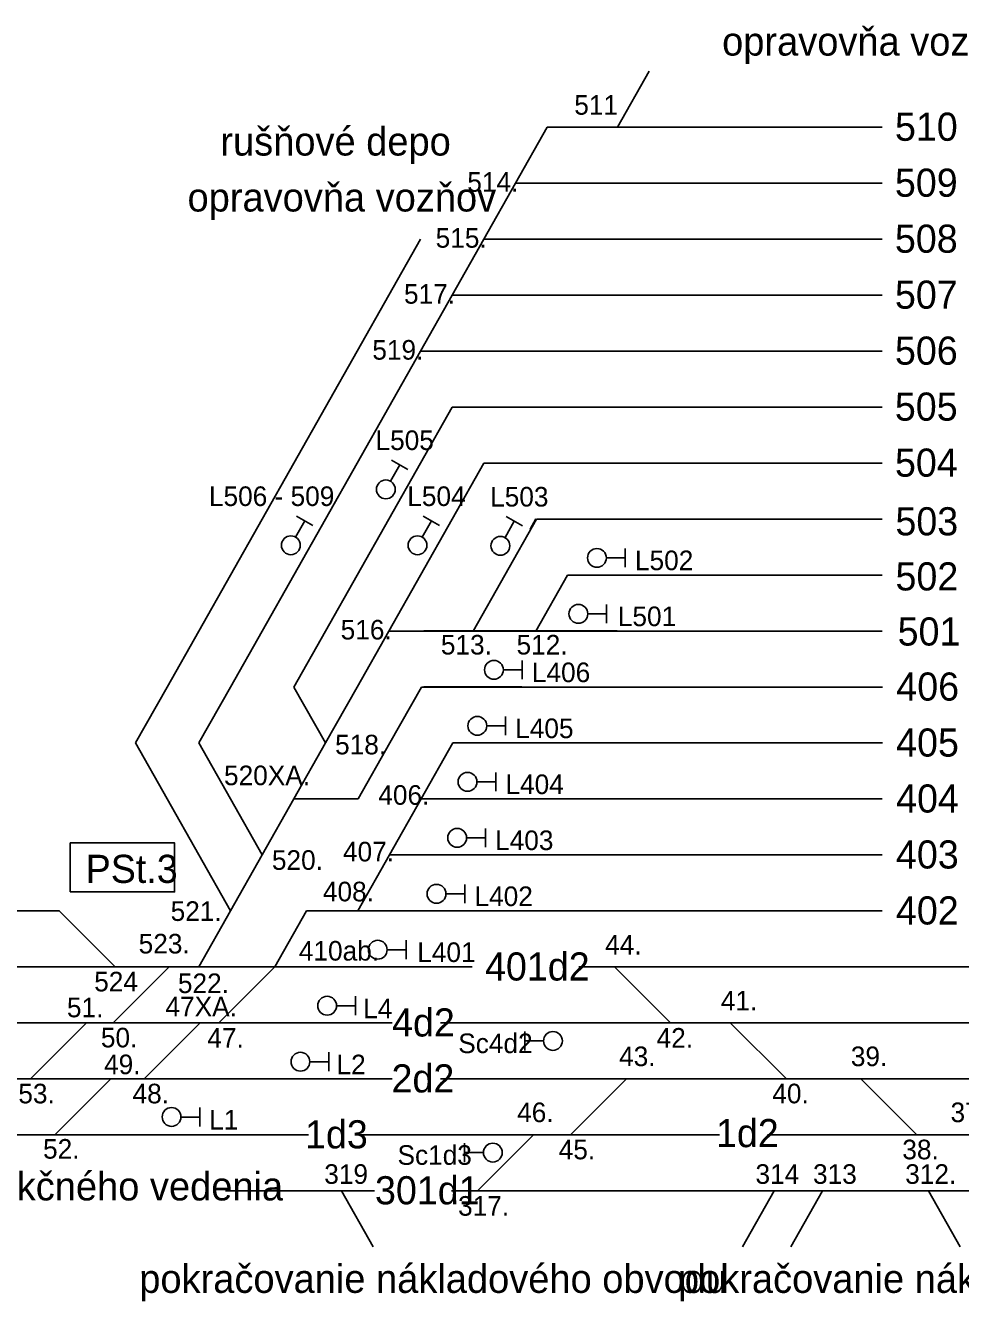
# Model space of a CAD drawing. Extents: x -119 to 851, y -238 to 59.
# Drawn here: x 437.12 to 470.49, y -115.25 to -69.7 of the extents above; entities that cross this region are included whole.
import ezdxf

# ---------------------------------------------------------------- set-up
doc = ezdxf.new("R2010")
doc.units = 0
for name, color, linetype in [('budova', 7, 'Continuous'), ('Level 2', 7, 'Continuous'), ('netlač', 7, 'Continuous'), ('PU_navestidla', 7, 'Continuous'), ('PU_oznacenie navestidiel', 7, 'Continuous'), ('PU_stan_kolaje', 7, 'Continuous'), ('PU_vlecky', 7, 'Continuous')]:
    doc.layers.add(name, color=color, linetype=linetype)

msp = doc.modelspace()

# ---------------------------------------------------------------- linework, layer by layer
at = {"layer": 'budova'}
msp.add_lwpolyline([(438.715, -100.631), (442.443, -100.631), (442.443, -98.882), (438.715, -98.882)], close=True, dxfattribs=at)
msp.add_lwpolyline([(438.715, -100.631), (442.443, -100.631), (442.443, -98.882), (438.715, -98.882)], close=True, dxfattribs=at)
at = {"layer": 'Level 2'}
for p, q in [((458.236, -91.313), (451.337, -91.313)), ((458.236, -91.313), (451.337, -91.313)), ((454.836, -93.312), (451.337, -93.312)), ((454.836, -93.312), (451.337, -93.312)), ((453.736, -99.309), (450.114, -99.309)), ((453.736, -99.309), (450.114, -99.309)), ((438.339, -101.308), (436.556, -101.308)), ((438.339, -101.308), (436.556, -101.308)), ((447.937, -101.308), (447.837, -101.308)), ((447.937, -101.308), (447.837, -101.308)), ((452.836, -101.308), (447.937, -101.308)), ((452.836, -101.308), (447.937, -101.308)), ((436.556, -103.307), (442.248, -103.307)), ((436.556, -103.307), (442.248, -103.307)), ((421.041, -107.305), (450.209, -107.305)), ((421.041, -107.305), (450.209, -107.305)), ((451.932, -107.305), (474.492, -107.305)), ((451.932, -107.305), (474.492, -107.305)), ((444.263, -111.303), (449.573, -111.303)), ((444.263, -111.303), (449.573, -111.303))]:
    msp.add_line(p, q, dxfattribs=at)
msp.add_lwpolyline([(455.132, -87.681), (455.336, -87.315)], dxfattribs=at)
msp.add_lwpolyline([(455.132, -87.681), (455.336, -87.315)], dxfattribs=at)
at = {"layer": 'netlač'}
for p, q in [((455.734, -73.33), (467.694, -73.33)), ((454.604, -75.328), (467.694, -75.328)), ((454.604, -75.328), (467.694, -75.328)), ((453.474, -77.327), (467.694, -77.327)), ((453.474, -77.327), (467.694, -77.327)), ((452.344, -79.325), (467.694, -79.325)), ((452.344, -79.325), (467.694, -79.325)), ((451.214, -81.324), (467.694, -81.324)), ((451.214, -81.324), (467.694, -81.324)), ((467.694, -83.32), (452.344, -83.322)), ((467.694, -83.32), (452.344, -83.322)), ((453.474, -85.321), (467.694, -85.321)), ((453.474, -85.321), (467.694, -85.321)), ((455.36, -87.319), (467.694, -87.319)), ((455.36, -87.319), (467.694, -87.319)), ((456.461, -89.318), (467.694, -89.318)), ((456.461, -89.318), (467.694, -89.318)), ((450.085, -91.316), (467.694, -91.316)), ((450.085, -91.316), (467.694, -91.316)), ((451.249, -93.315), (467.711, -93.315)), ((451.249, -93.315), (467.711, -93.315)), ((452.373, -95.313), (467.706, -95.313)), ((452.373, -95.313), (467.706, -95.313)), ((446.695, -97.311), (448.989, -97.311)), ((446.695, -97.311), (448.989, -97.311)), ((451.243, -97.312), (467.702, -97.312)), ((451.243, -97.312), (467.702, -97.312)), ((450.113, -99.31), (467.698, -99.31)), ((450.113, -99.31), (467.698, -99.31)), ((447.155, -101.308), (467.694, -101.308)), ((447.155, -101.308), (467.694, -101.308)), ((442.248, -103.307), (453.064, -103.307)), ((442.248, -103.307), (453.064, -103.307)), ((456.871, -103.307), (473.479, -103.307)), ((456.871, -103.307), (473.479, -103.307)), ((450.209, -105.306), (427.162, -105.306)), ((450.209, -105.306), (427.162, -105.306)), ((474.492, -105.306), (451.932, -105.306)), ((474.492, -105.306), (451.932, -105.306)), ((447.22, -109.302), (421.041, -109.302)), ((447.22, -109.302), (421.041, -109.302)), ((448.964, -109.302), (461.887, -109.302)), ((448.964, -109.302), (461.887, -109.302)), ((463.603, -109.302), (474.492, -109.302)), ((463.603, -109.302), (474.492, -109.302)), ((484.296, -111.301), (452.322, -111.301)), ((484.296, -111.301), (452.322, -111.301))]:
    msp.add_line(p, q, dxfattribs=at)
at = {"layer": 'PU_navestidla'}
for p, q in [((450.479, -85.38), (450.148, -85.965)), ((450.479, -85.38), (450.148, -85.965)), ((450.185, -85.214), (450.77, -85.545)), ((450.185, -85.214), (450.77, -85.545)), ((447.089, -87.378), (446.758, -87.963)), ((447.089, -87.378), (446.758, -87.963)), ((446.795, -87.212), (447.38, -87.543)), ((446.795, -87.212), (447.38, -87.543)), ((451.609, -87.378), (451.278, -87.963)), ((451.609, -87.378), (451.278, -87.963)), ((451.315, -87.212), (451.9, -87.543)), ((451.315, -87.212), (451.9, -87.543)), ((454.567, -87.397), (454.237, -87.982)), ((454.567, -87.397), (454.237, -87.982)), ((454.274, -87.231), (454.859, -87.562)), ((454.274, -87.231), (454.859, -87.562)), ((458.525, -88.369), (458.525, -89.041)), ((458.525, -88.369), (458.525, -89.041)), ((458.525, -88.706), (457.853, -88.706)), ((458.525, -88.706), (457.853, -88.706)), ((457.862, -90.367), (457.862, -91.039)), ((457.862, -90.367), (457.862, -91.039)), ((457.862, -90.705), (457.19, -90.705)), ((457.862, -90.705), (457.19, -90.705)), ((454.849, -92.366), (454.849, -93.038)), ((454.849, -92.366), (454.849, -93.038)), ((454.849, -92.704), (454.177, -92.704)), ((454.849, -92.704), (454.177, -92.704)), ((454.255, -94.702), (453.583, -94.702)), ((454.255, -94.702), (453.583, -94.702)), ((454.255, -94.365), (454.255, -95.037)), ((454.255, -94.365), (454.255, -95.037)), ((453.905, -96.363), (453.905, -97.035)), ((453.905, -96.363), (453.905, -97.035)), ((453.905, -96.701), (453.233, -96.701)), ((453.905, -96.701), (453.233, -96.701)), ((453.535, -98.363), (453.535, -99.035)), ((453.535, -98.363), (453.535, -99.035)), ((453.535, -98.7), (452.863, -98.7)), ((453.535, -98.7), (452.863, -98.7)), ((452.799, -100.361), (452.799, -101.033)), ((452.799, -100.361), (452.799, -101.033)), ((452.799, -100.699), (452.127, -100.699)), ((452.799, -100.699), (452.127, -100.699)), ((450.701, -102.359), (450.701, -103.031)), ((450.701, -102.359), (450.701, -103.031)), ((450.701, -102.696), (450.029, -102.696)), ((450.701, -102.696), (450.029, -102.696)), ((448.894, -104.694), (448.222, -104.694)), ((448.894, -104.694), (448.222, -104.694)), ((448.894, -104.357), (448.894, -105.029)), ((448.894, -104.357), (448.894, -105.029)), ((454.938, -106.287), (454.938, -105.615)), ((454.938, -106.287), (454.938, -105.615)), ((454.938, -105.949), (455.61, -105.949)), ((454.938, -105.949), (455.61, -105.949)), ((447.941, -106.356), (447.941, -107.028)), ((447.941, -106.356), (447.941, -107.028)), ((447.941, -106.693), (447.269, -106.693)), ((447.941, -106.693), (447.269, -106.693)), ((443.342, -108.331), (443.342, -109.002)), ((443.342, -108.331), (443.342, -109.002)), ((443.342, -108.668), (442.67, -108.668)), ((443.342, -108.668), (442.67, -108.668)), ((452.792, -110.275), (452.792, -109.603)), ((452.792, -110.275), (452.792, -109.603)), ((452.792, -109.937), (453.464, -109.937)), ((452.792, -109.937), (453.464, -109.937))]:
    msp.add_line(p, q, dxfattribs=at)
for centre in [(449.981, -86.257), (449.981, -86.257), (446.592, -88.255), (446.592, -88.255), (451.111, -88.255), (451.111, -88.255), (454.07, -88.274), (454.07, -88.274), (457.517, -88.705), (457.517, -88.705), (456.854, -90.703), (456.854, -90.703), (453.841, -92.702), (453.841, -92.702), (453.247, -94.701), (453.247, -94.701), (452.897, -96.699), (452.897, -96.699), (452.527, -98.699), (452.527, -98.699), (451.791, -100.697), (451.791, -100.697), (449.693, -102.695), (449.693, -102.695), (447.886, -104.693), (447.886, -104.693), (455.946, -105.951), (455.946, -105.951), (446.933, -106.692), (446.933, -106.692), (442.334, -108.666), (442.334, -108.666), (453.8, -109.939), (453.8, -109.939)]:
    msp.add_circle(centre, 0.336, dxfattribs=at)
at = {"layer": 'PU_stan_kolaje'}
for points in [[(458.246, -73.33), (459.375, -71.331)], [(454.604, -75.328), (455.734, -73.33)], [(454.604, -75.328), (455.734, -73.33)], [(453.474, -77.327), (454.604, -75.328)], [(453.474, -77.327), (454.604, -75.328)], [(450.085, -79.325), (451.214, -77.327)], [(450.085, -79.325), (451.214, -77.327)], [(452.344, -79.325), (453.474, -77.327)], [(452.344, -79.325), (453.474, -77.327)], [(448.955, -81.324), (450.085, -79.325)], [(448.955, -81.324), (450.085, -79.325)], [(451.214, -81.324), (452.344, -79.325)], [(451.214, -81.324), (452.344, -79.325)], [(447.825, -83.322), (448.955, -81.324)], [(447.825, -83.322), (448.955, -81.324)], [(450.085, -83.322), (451.214, -81.324)], [(450.085, -83.322), (451.214, -81.324)], [(446.695, -85.321), (447.825, -83.322)], [(446.695, -85.321), (447.825, -83.322)], [(448.955, -85.321), (450.085, -83.322)], [(448.955, -85.321), (450.085, -83.322)], [(451.214, -85.321), (452.344, -83.322)], [(451.214, -85.321), (452.344, -83.322)], [(445.565, -87.319), (446.695, -85.321)], [(445.565, -87.319), (446.695, -85.321)], [(447.825, -87.319), (448.955, -85.321)], [(447.825, -87.319), (448.955, -85.321)], [(450.085, -87.319), (451.214, -85.321)], [(450.085, -87.319), (451.214, -85.321)], [(452.344, -87.319), (453.474, -85.321)], [(452.344, -87.319), (453.474, -85.321)], [(444.435, -89.318), (445.565, -87.319)], [(444.435, -89.318), (445.565, -87.319)], [(446.695, -89.318), (447.825, -87.319)], [(446.695, -89.318), (447.825, -87.319)], [(448.955, -89.318), (450.085, -87.319)], [(448.955, -89.318), (450.085, -87.319)], [(451.214, -89.318), (452.344, -87.319)], [(451.214, -89.318), (452.344, -87.319)], [(454.23, -89.318), (455.36, -87.319)], [(454.23, -89.318), (455.36, -87.319)], [(443.305, -91.316), (444.435, -89.318)], [(443.305, -91.316), (444.435, -89.318)], [(445.565, -91.316), (446.695, -89.318)], [(445.565, -91.316), (446.695, -89.318)], [(447.825, -91.316), (448.955, -89.318)], [(447.825, -91.316), (448.955, -89.318)], [(450.085, -91.316), (451.214, -89.318)], [(450.085, -91.316), (451.214, -89.318)], [(453.1, -91.316), (454.23, -89.318)], [(453.1, -91.316), (454.23, -89.318)], [(455.331, -91.316), (456.461, -89.318)], [(455.331, -91.316), (456.461, -89.318)], [(442.175, -93.315), (443.305, -91.316)], [(442.175, -93.315), (443.305, -91.316)], [(444.435, -93.315), (445.565, -91.316)], [(444.435, -93.315), (445.565, -91.316)], [(446.695, -93.315), (447.825, -91.316)], [(446.695, -93.315), (447.825, -91.316)], [(448.955, -93.315), (450.085, -91.316)], [(448.955, -93.315), (450.085, -91.316)], [(441.045, -95.313), (442.175, -93.315)], [(441.045, -95.313), (442.175, -93.315)], [(443.305, -95.313), (444.435, -93.315)], [(443.305, -95.313), (444.435, -93.315)], [(446.695, -93.315), (447.825, -95.313)], [(446.695, -93.315), (447.825, -95.313)], [(447.825, -95.313), (448.955, -93.315)], [(447.825, -95.313), (448.955, -93.315)], [(450.119, -95.313), (451.249, -93.315)], [(450.119, -95.313), (451.249, -93.315)], [(441.045, -95.313), (442.175, -97.311)], [(441.045, -95.313), (442.175, -97.311)], [(443.305, -95.313), (444.435, -97.311)], [(443.305, -95.313), (444.435, -97.311)], [(446.695, -97.311), (447.825, -95.313)], [(446.695, -97.311), (447.825, -95.313)], [(448.989, -97.311), (450.119, -95.313)], [(448.989, -97.311), (450.119, -95.313)], [(451.243, -97.312), (452.374, -95.312)], [(451.243, -97.312), (452.374, -95.312)], [(442.175, -97.311), (443.305, -99.31)], [(442.175, -97.311), (443.305, -99.31)], [(444.435, -97.311), (445.565, -99.31)], [(444.435, -97.311), (445.565, -99.31)], [(445.565, -99.31), (446.695, -97.311)], [(445.565, -99.31), (446.695, -97.311)], [(450.114, -99.309), (451.244, -97.31)], [(450.114, -99.309), (451.244, -97.31)], [(443.305, -99.31), (444.435, -101.308)], [(443.305, -99.31), (444.435, -101.308)], [(444.435, -101.308), (445.565, -99.31)], [(444.435, -101.308), (445.565, -99.31)], [(448.983, -101.309), (450.113, -99.31)], [(448.983, -101.309), (450.113, -99.31)], [(438.325, -101.308), (440.324, -103.307)], [(438.325, -101.308), (440.324, -103.307)], [(443.305, -103.307), (444.435, -101.308)], [(443.305, -103.307), (444.435, -101.308)], [(446.025, -103.307), (447.155, -101.308)], [(446.025, -103.307), (447.155, -101.308)], [(442.248, -103.307), (440.249, -105.306)], [(442.248, -103.307), (440.249, -105.306)], [(446.025, -103.307), (444.026, -105.306)], [(446.025, -103.307), (444.026, -105.306)], [(458.146, -103.305), (460.145, -105.304)], [(458.146, -103.305), (460.145, -105.304)], [(439.301, -105.306), (437.302, -107.305)], [(439.301, -105.306), (437.302, -107.305)], [(443.356, -105.306), (441.357, -107.305)], [(443.356, -105.306), (441.357, -107.305)], [(462.276, -105.304), (464.276, -107.305)], [(462.276, -105.304), (464.276, -107.305)], [(440.16, -107.305), (438.185, -109.28)], [(440.16, -107.305), (438.185, -109.28)], [(458.566, -107.305), (456.568, -109.302)], [(458.566, -107.305), (456.568, -109.302)], [(466.94, -107.305), (468.937, -109.302)], [(466.94, -107.305), (468.937, -109.302)], [(455.256, -109.302), (453.257, -111.301)], [(455.256, -109.302), (453.257, -111.301)], [(448.396, -111.301), (449.526, -113.299)], [(448.396, -111.301), (449.526, -113.299)], [(462.71, -113.3), (463.84, -111.301)], [(462.71, -113.3), (463.84, -111.301)], [(464.441, -113.3), (465.571, -111.301)], [(464.441, -113.3), (465.571, -111.301)], [(469.356, -111.301), (470.485, -113.299)], [(469.356, -111.301), (470.485, -113.299)]]:
    msp.add_lwpolyline(points, dxfattribs=at)

# ---------------------------------------------------------------- texts
at = {"layer": 'budova'}
msp.add_text('PSt.3', height=1.0044, dxfattribs=at).set_placement((439.268, -100.309))
msp.add_text('PSt.3', height=1.0044, dxfattribs=at).set_placement((439.268, -100.309))
at = {"layer": 'PU_oznacenie navestidiel'}
for s, p in [('511', (456.707, -72.881)), ('514.', (452.889, -75.631)), ('514.', (452.889, -75.631)), ('515.', (451.759, -77.629)), ('515.', (451.759, -77.629)), ('517.', (450.629, -79.628)), ('517.', (450.629, -79.628)), ('519.', (449.499, -81.626)), ('519.', (449.499, -81.626)), ('L505', (449.613, -84.853)), ('L505', (449.613, -84.853)), ('L506 - 509', (443.667, -86.852)), ('L506 - 509', (443.667, -86.852)), ('L504', (450.746, -86.852)), ('L504', (450.746, -86.852)), ('L503', (453.704, -86.871)), ('L503', (453.704, -86.871)), ('L502', (458.873, -89.143)), ('L502', (458.873, -89.143)), ('L501', (458.262, -91.141)), ('L501', (458.262, -91.141)), ('516.', (448.369, -91.618)), ('516.', (448.369, -91.618)), ('513.', (451.946, -92.154)), ('513.', (451.946, -92.154)), ('512.', (454.647, -92.154)), ('512.', (454.647, -92.154)), ('L406', (455.194, -93.141)), ('L406', (455.194, -93.141)), ('L405', (454.598, -95.139)), ('L405', (454.598, -95.139)), ('518.', (448.17, -95.72)), ('518.', (448.17, -95.72)), ('520XA.', (444.206, -96.82)), ('520XA.', (444.206, -96.82)), ('L404', (454.251, -97.137)), ('L404', (454.251, -97.137)), ('406.', (449.713, -97.519)), ('406.', (449.713, -97.519)), ('407.', (448.452, -99.542)), ('407.', (448.452, -99.542)), ('L403', (453.881, -99.137)), ('L403', (453.881, -99.137)), ('520.', (445.915, -99.842)), ('520.', (445.915, -99.842)), ('408.', (447.735, -100.967)), ('408.', (447.735, -100.967)), ('L402', (453.146, -101.135)), ('L402', (453.146, -101.135)), ('521.', (442.301, -101.666)), ('521.', (442.301, -101.666)), ('523.', (441.159, -102.828)), ('523.', (441.159, -102.828)), ('410ab.', (446.877, -103.082)), ('410ab.', (446.877, -103.082)), ('L401', (451.102, -103.133)), ('L401', (451.102, -103.133)), ('44.', (457.808, -102.865)), ('44.', (457.808, -102.865)), ('524', (439.572, -104.182)), ('524', (439.572, -104.182)), ('522.', (442.56, -104.242)), ('522.', (442.56, -104.242)), ('41.', (461.938, -104.864)), ('41.', (461.938, -104.864)), ('51.', (438.599, -105.106)), ('51.', (438.599, -105.106)), ('47XA.', (442.116, -105.072)), ('47XA.', (442.116, -105.072)), ('L4', (449.172, -105.143)), ('L4', (449.172, -105.143)), ('50.', (439.81, -106.181)), ('50.', (439.81, -106.181)), ('47.', (443.61, -106.192)), ('47.', (443.61, -106.192)), ('Sc4d2', (452.566, -106.386)), ('Sc4d2', (452.566, -106.386)), ('42.', (459.646, -106.191)), ('42.', (459.646, -106.191)), ('43.', (458.307, -106.851)), ('43.', (458.307, -106.851)), ('39.', (466.578, -106.851)), ('39.', (466.578, -106.851)), ('49.', (439.924, -107.138)), ('49.', (439.924, -107.138)), ('L2', (448.221, -107.142)), ('L2', (448.221, -107.142)), ('53.', (436.864, -108.18)), ('53.', (436.864, -108.18)), ('48.', (440.941, -108.18)), ('48.', (440.941, -108.18)), ('40.', (463.776, -108.178)), ('40.', (463.776, -108.178)), ('L1', (443.675, -109.116)), ('L1', (443.675, -109.116)), ('46.', (454.668, -108.85)), ('46.', (454.668, -108.85)), ('37.', (470.137, -108.85)), ('37.', (470.137, -108.85)), ('52.', (437.747, -110.154)), ('52.', (437.747, -110.154)), ('Sc1d3', (450.398, -110.374)), ('Sc1d3', (450.398, -110.374)), ('45.', (456.152, -110.177)), ('45.', (456.152, -110.177)), ('38.', (468.416, -110.177)), ('38.', (468.416, -110.177)), ('319', (447.784, -111.053)), ('319', (447.784, -111.053)), ('314', (463.175, -111.053)), ('314', (463.175, -111.053)), ('313', (465.229, -111.053)), ('313', (465.229, -111.053)), ('312.', (468.52, -111.053)), ('312.', (468.52, -111.053)), ('317.', (452.559, -112.191)), ('317.', (452.559, -112.191))]:
    msp.add_text(s, height=0.7, dxfattribs=at).set_placement(p)
at = {"layer": 'PU_stan_kolaje'}
for s, p in [('510', (468.153, -73.812)), ('510', (468.153, -73.812)), ('509', (468.151, -75.81)), ('509', (468.151, -75.81)), ('508', (468.151, -77.809)), ('508', (468.151, -77.809)), ('507', (468.152, -79.807)), ('507', (468.152, -79.807)), ('506', (468.152, -81.806)), ('506', (468.152, -81.806)), ('505', (468.149, -83.805)), ('505', (468.149, -83.805)), ('504', (468.153, -85.805)), ('504', (468.153, -85.805)), ('503', (468.169, -87.9)), ('503', (468.169, -87.9)), ('502', (468.172, -89.867)), ('502', (468.172, -89.867)), ('501', (468.248, -91.834)), ('501', (468.248, -91.834)), ('406', (468.201, -93.8)), ('406', (468.201, -93.8)), ('405', (468.194, -95.799)), ('405', (468.194, -95.799)), ('404', (468.194, -97.797)), ('404', (468.194, -97.797)), ('403', (468.189, -99.795)), ('403', (468.189, -99.795)), ('402', (468.188, -101.794)), ('402', (468.188, -101.794)), ('401d2', (453.521, -103.794)), ('401d2', (453.521, -103.794)), ('4d2', (450.204, -105.792)), ('4d2', (450.204, -105.792)), ('2d2', (450.185, -107.79)), ('2d2', (450.185, -107.79)), ('1d3', (447.097, -109.787)), ('1d3', (447.097, -109.787)), ('1d2', (461.765, -109.743)), ('1d2', (461.765, -109.743)), ('301d1', (449.594, -111.785)), ('301d1', (449.594, -111.785))]:
    msp.add_text(s, height=1.0044, dxfattribs=at).set_placement(p)
at = {"layer": 'PU_vlecky'}
for s, p in [('opravovňa vozňov', (461.984, -70.77)), ('rušňové depo', (444.075, -74.339)), ('rušňové depo', (444.075, -74.339)), ('opravovňa vozňov', (442.903, -76.337)), ('opravovňa vozňov', (442.903, -76.337)), ('opravovňa trakčného vedenia', (428.508, -111.646)), ('opravovňa trakčného vedenia', (428.508, -111.646)), ('pokračovanie nákladového obvodu', (441.181, -114.947)), ('pokračovanie nákladového obvodu', (441.181, -114.947)), ('pokračovanie nákladového obvodu', (460.408, -114.947)), ('pokračovanie nákladového obvodu', (460.408, -114.947))]:
    msp.add_text(s, height=1.015, dxfattribs=at).set_placement(p)

doc.saveas('drawing.dxf')
